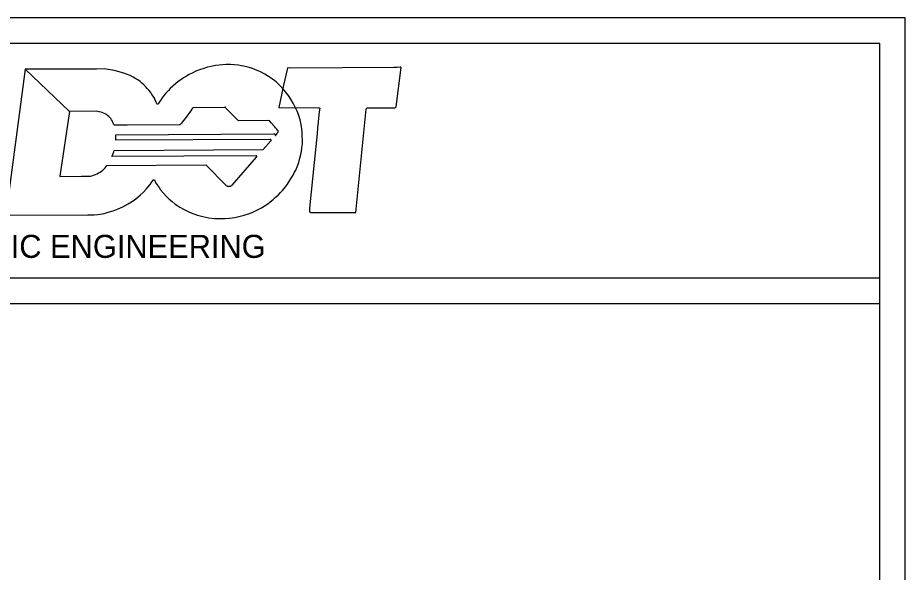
# Model space of a CAD drawing. Extents: x 187716 to 188418, y 178603 to 179533.
# Drawn here: x 188037.5 to 188418.1, y 179295.2 to 179533 of the extents above; entities that cross this region are included whole.
import ezdxf

# ---------------------------------------------------------------- set-up
doc = ezdxf.new("R2010")
doc.units = 0
doc.layers.add('Default', color=7, linetype='Continuous')

msp = doc.modelspace()

# ---------------------------------------------------------------- linework, layer by layer
at = {"layer": 'Default'}
for p, q in [((188059.66, 179492.88), (188040.61, 179511)), ((188059.66, 179492.88), (188059.66, 179492.88)), ((188079.5, 179482.86), (188147.14, 179483.19)), ((188075.73, 179469.68), (188118.16, 179469.88)), ((187727.02, 179421.53), (188407.12, 179421.53)), ((187727.02, 179410.49), (188407.12, 179410.49))]:
    msp.add_line(p, q, dxfattribs=at)
for points in [[(188418.09, 178602.69), (188418.09, 179533.02), (187715.97, 179533.02), (187715.97, 178602.69)], [(188407.12, 178613.73), (188407.12, 179522.02), (187727.02, 179522.02), (187727.02, 178613.73)]]:
    msp.add_lwpolyline(points, close=True, dxfattribs=at)
for points in [[(188141.62, 179509.85), (188140.16, 179510.42), (188138.17, 179511.2), (188136.68, 179511.61), (188134.98, 179512.06), (188133.53, 179512.4), (188132.01, 179512.62), (188130.41, 179512.8), (188128.69, 179512.92), (188126.8, 179512.92), (188125.23, 179512.8), (188123.84, 179512.74), (188122.26, 179512.52), (188120.49, 179512.13), (188118.88, 179511.78), (188117.31, 179511.32), (188115.48, 179510.7), (188113.82, 179510.04), (188112.28, 179509.27), (188110.98, 179508.67), (188109.8, 179507.99), (188108.51, 179507.2), (188107.46, 179506.44), (188106.33, 179505.63), (188105.15, 179504.71), (188103.95, 179503.67), (188102.91, 179502.68), (188102.12, 179501.79), (188101.04, 179500.64), (188100.21, 179499.77), (188099.39, 179498.69), (188098.71, 179497.56), (188098.13, 179496.77), (188097.72, 179496.07), (188097.47, 179495.89), (188097.31, 179495.89), (188097.17, 179496.05), (188096.99, 179496.43), (188096.78, 179496.92), (188096.48, 179497.73), (188096.08, 179498.51), (188095.55, 179499.34), (188095.01, 179500.15), (188094.53, 179500.89), (188093.73, 179501.92), (188093, 179502.7), (188092.34, 179503.48), (188091.42, 179504.37), (188090.68, 179505.02), (188089.96, 179505.64), (188088.94, 179506.4), (188088.14, 179506.88), (188086.98, 179507.58), (188085.77, 179508.18), (188084.19, 179508.79), (188082.96, 179509.31), (188081.46, 179509.74), (188079.95, 179510.15), (188078.18, 179510.55), (188076.32, 179510.86), (188074.51, 179511.09), (188071.2, 179511.03), (188040.61, 179511)], [(188187.2, 179494.35), (188199.22, 179494.43), (188199.51, 179494.48), (188199.62, 179494.62), (188199.71, 179494.86), (188201.89, 179511.75), (188201.8, 179511.76), (188201.63, 179511.83), (188201.46, 179511.76), (188200.21, 179511.66), (188198.75, 179511.66), (188154.4, 179511.46), (188153.5, 179511.48), (188153.29, 179511.48), (188153.16, 179511.37), (188153.04, 179510.78), (188151.45, 179504.04), (188149.42, 179494.54)], [(188040.61, 179511), (188032.32, 179448.32), (188067.59, 179448.46), (188070.26, 179448.56), (188071.77, 179448.59), (188072.82, 179448.76), (188074.56, 179449.06), (188076.27, 179449.57), (188078.4, 179450.18), (188080.6, 179451.08), (188082.52, 179451.94), (188084.87, 179453.16), (188087.38, 179454.84), (188088.98, 179456.08), (188090.08, 179457.08), (188091.4, 179458.23), (188092.63, 179459.49), (188093.39, 179460.45), (188094.25, 179461.54), (188095.06, 179462.7), (188095.67, 179463.54), (188096.11, 179463.54), (188096.48, 179462.81), (188096.76, 179462.14), (188097.27, 179461.34), (188098.07, 179460.17), (188098.77, 179459.25), (188099.84, 179457.89), (188101.24, 179456.42), (188102.48, 179455.22), (188103.7, 179454.16), (188104.93, 179453.14), (188106.1, 179452.41), (188107.05, 179451.73), (188108.58, 179450.87), (188110.53, 179449.86), (188112.14, 179449.16), (188114.62, 179448.39), (188116.92, 179447.76), (188119.43, 179447.19), (188121.87, 179446.93), (188123.99, 179446.93), (188126.45, 179446.93), (188128.3, 179447.04), (188130.57, 179447.39), (188132.26, 179447.78), (188134.54, 179448.35), (188136.44, 179448.97), (188138.24, 179449.68), (188140.02, 179450.55), (188141.67, 179451.35), (188143.1, 179452.25), (188144.68, 179453.27), (188145.79, 179454.05), (188146.99, 179455.01), (188148.06, 179456.05), (188149.12, 179456.97), (188150.12, 179458.02), (188151.02, 179458.96), (188152.32, 179460.49), (188153.19, 179461.67), (188154.04, 179463.02), (188154.76, 179464.23), (188155.53, 179465.49), (188156.23, 179466.77), (188156.7, 179467.67), (188157.32, 179469.13), (188157.96, 179470.93), (188158.48, 179472.77), (188158.93, 179474.35), (188159.11, 179475.72), (188159.38, 179477.27), (188159.55, 179478.96), (188159.42, 179483.81), (188159.35, 179485.27)], [(188059.66, 179492.88), (188055.52, 179465.13), (188055.52, 179464.93), (188064.88, 179465.03), (188067.81, 179465.03), (188068.64, 179465.08), (188069.2, 179465.2), (188069.99, 179465.46), (188070.82, 179465.75), (188071.52, 179466.06), (188072.19, 179466.47), (188072.81, 179466.85), (188073.46, 179467.24), (188073.94, 179467.67), (188074.51, 179468.16), (188074.97, 179468.72), (188075.36, 179469.23), (188075.73, 179469.68)], [(188071.1, 179492.92), (188059.66, 179492.88)], [(188147.14, 179483.19), (188147.71, 179483.19), (188147.78, 179483.14), (188147.86, 179483.11), (188147.89, 179482.99), (188147.92, 179482.7), (188148, 179482.53), (188148.04, 179482.49), (188148.14, 179482.49), (188148.22, 179482.61), (188148.35, 179482.77), (188148.54, 179483.09), (188148.76, 179483.48), (188148.92, 179483.81), (188149.11, 179483.93), (188149.12, 179483.98), (188149.17, 179484.23), (188149.17, 179484.38), (188149.1, 179484.52), (188148.91, 179484.76), (188148.59, 179485.3), (188148.09, 179485.85), (188147.59, 179486.35), (188146.2, 179487.92), (188145.65, 179488.62), (188145.39, 179488.82), (188145.2, 179488.94), (188132.16, 179488.82), (188126.84, 179494.11), (188126.7, 179494.3), (188126.64, 179494.53), (188126.6, 179494.61), (188126.48, 179494.61), (188126.31, 179494.53), (188125.97, 179494.49), (188113.01, 179494.41), (188112.75, 179494.32), (188112.44, 179494.23), (188112.31, 179494.04), (188112.14, 179493.71), (188111.59, 179492.95), (188110.85, 179491.98), (188110, 179490.87), (188109.27, 179489.85), (188108.41, 179488.82), (188107.66, 179487.83), (188107.04, 179487.09), (188106.75, 179487.09), (188084.39, 179486.96), (188078.77, 179486.94)], [(188149.42, 179494.54), (188166.64, 179494.43), (188166.86, 179494.45), (188167.01, 179494.25), (188166.82, 179492.65), (188166.51, 179489.89), (188166.35, 179488.29), (188166.1, 179485.78), (188165.86, 179483.26), (188164.55, 179471.01), (188162.58, 179451.4), (188162.54, 179450.05), (188162.72, 179449.65), (188163, 179449.49), (188182.5, 179449.49), (188186.87, 179493.83), (188187, 179494.15), (188187.2, 179494.35)], [(188146.02, 179480.19), (188146.02, 179480.2), (188146.05, 179480.21), (188146.1, 179480.26), (188146.11, 179480.27), (188146.11, 179480.28), (188146.11, 179480.28), (188146.12, 179480.28), (188146.12, 179480.29), (188146.12, 179480.3), (188146.12, 179480.36), (188146.12, 179480.36), (188146.12, 179480.36), (188146.12, 179480.37), (188146.12, 179480.39), (188146.12, 179480.4), (188146.12, 179480.43), (188146.12, 179480.43), (188146.12, 179480.45), (188146.12, 179480.46), (188146.12, 179480.46), (188146.12, 179480.46), (188146.12, 179480.47), (188146.12, 179480.54), (188146.12, 179480.54), (188146.12, 179480.57), (188146.12, 179480.57), (188146.12, 179480.57), (188146.11, 179480.57), (188146.11, 179480.6), (188146.11, 179480.6), (188146.1, 179480.61), (188146.09, 179480.61), (188146.05, 179480.62), (188146.03, 179480.62), (188146.02, 179480.62), (188146.02, 179480.62), (188146.02, 179480.66), (188146.02, 179480.67), (188146.01, 179480.71), (188145.99, 179480.72), (188145.99, 179480.74), (188145.99, 179480.74), (188145.99, 179480.74), (188145.99, 179480.74), (188145.96, 179480.76), (188145.95, 179480.76), (188145.94, 179480.76), (188145.88, 179480.76), (188145.88, 179480.76), (188145.86, 179480.76), (188145.86, 179480.76), (188145.86, 179480.76), (188145.83, 179480.76), (188145.82, 179480.76), (188145.82, 179480.76), (188145.82, 179480.76), (188145.82, 179480.78), (188145.81, 179480.78), (188145.78, 179480.78), (188145.78, 179480.78), (188079.51, 179480.49)], [(188142.76, 179476.46), (188146.02, 179480.19)], [(188139.64, 179473.81), (188077.9, 179473.52)], [(188078.83, 179476.15), (188142.73, 179476.46)], [(188118.16, 179469.88), (188126.89, 179461.1), (188127.09, 179460.93), (188127.34, 179460.84), (188127.92, 179460.8), (188128.25, 179460.8), (188128.67, 179460.82), (188128.98, 179460.91), (188129.21, 179461.02), (188129.42, 179461.28), (188139.91, 179473.19)]]:
    msp.add_lwpolyline(points, dxfattribs=at)
for centre, radius, start, end in [((188127.31, 179480.81), 32.34, 7.9062, 63.7281), ((188070.74, 179484.15), 8.75, 52.8307, 87.5642), ((188070.75, 179484.68), 8.33, 15.5689, 50.6828), ((188059.54, 179481.43), 20, 357.3256, 4.1293), ((188059.39, 179481.48), 20.16, 336.6718, 344.666), ((188139.64, 179473.43), 0.366, 318.7788, 90.2714)]:
    msp.add_arc(centre, radius, start, end, dxfattribs=at)

# ---------------------------------------------------------------- texts
msp.add_text('TRAFFIC ENGINEERING', height=9.8737, dxfattribs=at).set_placement((187991.95, 179430.04))

doc.saveas('drawing.dxf')
